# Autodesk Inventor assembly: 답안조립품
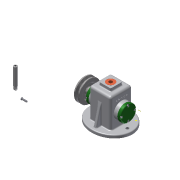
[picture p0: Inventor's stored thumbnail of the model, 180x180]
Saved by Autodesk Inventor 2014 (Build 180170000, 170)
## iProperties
Created: 2017-07
Part Number: 답안조립품
Document SubType Name: Assembly
Designer: user
Author: user
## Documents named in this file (16)
- C:\Users\user\Desktop\470708V1017\답안조립품.iam
- C:\Users\user\Desktop\470708V1017\470708V1017\V벨트풀리.ipt
- C:\Users\user\Desktop\470708V1017\470708V1017\고정핀 1.2 x  8.ipt
- C:\Users\user\Desktop\470708V1017\470708V1017\뒤커버.ipt
- C:\Users\user\Desktop\470708V1017\470708V1017\링크.ipt
- C:\Users\user\Desktop\470708V1017\470708V1017\멈춤나사 M3x8.ipt
- C:\Users\user\Desktop\470708V1017\470708V1017\베어링 12 x 32 x 10.ipt
- C:\Users\user\Desktop\470708V1017\470708V1017\본체.ipt
- C:\Users\user\Desktop\470708V1017\470708V1017\볼트 M4 x 12.ipt
- C:\Users\user\Desktop\470708V1017\470708V1017\부시.ipt
- C:\Users\user\Desktop\470708V1017\470708V1017\슬라이드.ipt
- C:\Users\user\Desktop\470708V1017\470708V1017\앞커버.ipt
- C:\Users\user\Desktop\470708V1017\470708V1017\오일실 12 25 7.ipt
- C:\Users\user\Desktop\470708V1017\470708V1017\키 4 x 4 x 10.ipt
- C:\Users\user\Desktop\470708V1017\470708V1017\편심축.ipt
- C:\Users\user\Desktop\470708V1017\470708V1017\핀 5 x 18.ipt
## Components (3 placed, 3 different names)
1. V벨트풀리:1
2. 고정핀 1.2 x  8:1
3. 핀 5 x 18:1
